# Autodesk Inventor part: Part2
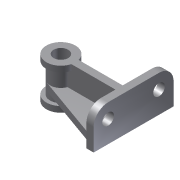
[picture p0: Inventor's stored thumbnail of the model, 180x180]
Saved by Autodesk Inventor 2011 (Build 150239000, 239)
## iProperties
Shininess: 77.0
Length Units: 11269
Angle Units: 11279
Time Units: 11290
Mass Units: 11283
Length Display Precision: 3
Angle Display Precision: 2
Created: 2001-12
Part Number: Part2
Document SubType Name: Modeling
Density: 1 g/cm^3
Density: 0.0
Volumn: 0.0
Area: 0.0
PropertySet Name: Model Information
Control State: 0
Master: False
Checked Out: False
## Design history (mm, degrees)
sketch "Sketch1"
  geometry: L1 (67.049, 55)-(67.049, -55); L2 (60.402, -45.579)-(-27.979, -14.132); L3 (-27.979, 14.132)-(60.402, 45.579); A1 r 10 centre (57.049, -55) between (67.049, -55) and (60.402, -45.579); A2 r 15 centre (-22.951, 0) between (-27.979, 14.132) and (-27.979, -14.132); A3 r 10 centre (57.049, 55) between (60.402, 45.579) and (67.049, 55)
  constraints: 6 end point, 6 point on circle, 6 tangent, 3 centre point, 1 equal length, 1 equal radius, 1 vertical
  dimensions: "d0" = 15 radius of A2; "d1" = 10 radius of A1; "d2" = 90 distance from line of L1 A2.centre; "d3" = 110 distance of L1.start L1.end
extrude "Extrusion1" new body sketch "Sketch1" distance "d4" = 10; taper "d5" = 0 deg
sketch "Sketch2"
  geometry: L1 (0, 110)-(0, 0) reference; L2 (0, 0)-(-30, 0); L3 (-50, 20)-(-50, 90); L4 (-30, 110)-(0, 110); C1 r 8 at (-30, 90); C2 r 8 at (-30, 20); A1 r 20 centre (-30, 20) between (-50, 20) and (-30, 0); A2 r 20 centre (-30, 90) between (-30, 110) and (-50, 90)
  constraints: 6 end point, 4 centre point, 4 point on circle, 4 tangent, 3 perpendicular, 2 coincident, 1 equal radius, 1 parallel
  dimensions: "d6" = 20 radius of A2; "d7" = 50 distance between parallel lines of L1 L3; "d10" = 16 diameter of C1
extrude "Extrusion2" join sketch "Sketch2" distance "d8" = 10; taper "d9" = 0 deg
workplane "Work Plane1"
sketch "Sketch3"
  geometry: C1 r 15 at (-22.951, 0); A1 r 15 centre (-22.951, 0) between (-27.979, 14.132) and (-27.979, -14.132) reference
  constraints: 2 concentric, 1 centre point
extrude "Extrusion3" join sketch "Sketch3" distance "d12" = 56; taper "d13" = 0 deg
sketch "Sketch4"
  geometry: L1 (7.951, 40)-(-57.058, 40); L2 (7.951, 40)-(37.951, 40) reference; L3 (-67.049, 50)-(-67.049, 30) reference; L4 (-77.049, 0)-(-77.049, 30) reference; L5 (-67.049, 0)-(-77.049, 0) reference; A1 r 10 centre (-57.058, 50) between (-67.049, 49.599) and (-57.058, 40)
  constraints: 2 end point, 2 point on circle, 2 point on line, 1 centre point, 1 horizontal, 1 tangent
  dimensions: "d14" = 85 distance from line of L4 L1.start; "d15" = 50 distance from line of L5 A1.centre
feature "Rib1" sketch "Sketch4" dims "d16" = 1, "d17" = 10
sketch "Sketch5"
  geometry: C1 r 20 at (-22.951, 0); 1 further point
  constraints: 1 centre point, 1 coincident
  dimensions: "d18" = 40 diameter of C1
extrude "Extrusion4" join sketch "Sketch5" distance "d19" = 8; taper "d20" = 0 deg
workplane "Work Plane2"
mirror "Mirror1"
sketch "Sketch6"
  geometry: A1 r 20 centre (-22.951, 0) between (-3.586, 5) and (-3.586, -5) reference
hole "Hole1" sketch "Sketch6" at (-22.951, 0) diameter "d22" = 20; stored, may be unused: countersink angle "d26" = 82 deg, drill point angle "d28" = 118 deg; dims "d23" = 6, "d24" = 4, "d25" = 2, "d27" = 8
body "Solid1"
other parameters: "d21" = -28
